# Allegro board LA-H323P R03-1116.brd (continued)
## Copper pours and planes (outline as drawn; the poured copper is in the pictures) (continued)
LX_1.8V on BOTTOM (solid shape): 180.19,85.17 180.19,84.05 180.44,83.81 180.44,81.38 180.25,81.19 178.32,81.19 178.18,81.32 178.18,82.26 178.42,82.5 179.17,82.5 179.32,82.64 179.32,85.15 179.49,85.32 180.04,85.32
LX_1V on TOP (solid shape): 185.2,96.91 185.2,95.59 185.03,95.42 182.26,95.42 182.17,95.51 182.17,96.84 182.39,97.06 185.05,97.06
LX_1V on BOTTOM (solid shape): 189.1,96.69 189.1,96.11 188.74,95.76 187.96,95.76 187.89,95.83 187.89,96 188.03,96.14 188.03,96.64 188.13,96.75 189.05,96.75
LX_1V on BOTTOM (solid shape): 183.97,98.33 183.97,96.86 184.27,96.56 185.12,96.56 185.71,95.97 185.71,95.38 185.65,95.32 184.76,95.32 184.73,95.35 183.99,95.35 183.78,95.14 183.78,95.14 183.71,95.07 183.71,92.99 183.51,92.79 180.83,92.79 180.7,92.92 180.7,98.17 180.99,98.46 183.84,98.46
LX_1V on IN2 (solid shape): 189.12,96.62 189.12,95.68 188.94,95.5 184.21,95.5 184.1,95.61 184.1,96.6 184.24,96.74 189,96.74
LX_2.5V on BOTTOM (solid shape): 4.43,44.38 4.43,43.04 4.52,42.95 5.99,42.95 6.08,42.86 6.08,41.89 5.99,41.8 2.61,41.8 2.52,41.89 2.52,42.6 2.61,42.69 3.45,42.69 3.54,42.78 3.54,44.38 3.63,44.47 4.34,44.47
LX_3V on BOTTOM (solid shape): 190.8,117.57 190.8,116.62 190.59,116.42 189.83,116.42 189.75,116.5 189.75,116.67 189.85,116.77 189.85,117.61 189.98,117.74 190.63,117.74
LX_3V on BOTTOM (solid shape): 186.26,120.39 186.26,119.09 186.45,118.9 187.02,118.9 187.1,118.82 187.1,117.09 187.56,116.63 187.56,116.04 187.49,115.97 185.63,115.97 185.57,115.91 185.57,114.19 185.39,114.02 183.33,114.02 183.21,114.14 183.21,117.24 183.98,118.02 183.98,120.29 184.23,120.54 186.11,120.54
LX_3V on IN2 (solid shape): 190.78,117.62 190.78,116.67 190.78,116.67 190.61,116.49 185.87,116.49 185.76,116.6 185.76,117.6 185.9,117.73 190.66,117.73
LX_5V on TOP (solid shape): 182.84,107.93 182.84,106.36 182.71,106.23 180.93,106.23 180.81,106.36 180.81,108.02 181.01,108.23 182.54,108.23
LX_5V on BOTTOM (solid shape): 182.16,109.33 182.16,105.08 182.64,104.59 182.88,104.59 182.88,104.6 186.61,104.6 186.61,104.07 182.45,104.07 182.28,103.89 179.2,103.89 179.11,103.98 179.11,108.89 179.61,109.38 182.1,109.38
LX_CHG on TOP (solid shape): 179.37,53.68 179.37,50.96 179.15,50.74 177.82,50.74 177.63,50.93 177.63,53.6 177.77,53.74 179.31,53.74
LX_CHG on BOTTOM (solid shape): 177.15,55.24 177.15,53.38 177.9,52.62 177.9,51.71 178.26,51.35 180.88,51.35 180.88,50.39 180.84,50.35 177.69,50.35 177.03,51.01 174.77,51.01 174.48,51.31 174.48,55.23 174.54,55.29 177.1,55.29
LX_CHG on BOTTOM (solid shape): 193.5,57.23 194.36,57.23 194.41,57.18 194.41,56.98 194.37,56.94 193.33,56.94 193.18,57.09 192.32,57.09 191.92,57.48 190.73,57.48 190.64,57.58 190.64,58.04 190.76,58.16 192.57,58.16
LX_CHG on IN2 (solid shape): 193.9,57.91 193.9,57.34 193.78,57.22 192.21,57.22 192.07,57.35 192.07,57.35 192.07,57.92 192.21,58.06 193.75,58.06
LX_CHG on IN2 (solid shape): 179.25,52.13 179.25,51.96 178.12,50.83 177.97,50.83 177.95,50.85 177.55,51.25 177.55,51.45 178.63,52.53 178.85,52.53
LX_DDR on TOP (solid shape): 8.04,68.41 8.04,66.38 7.64,65.98 6.36,65.98 6.1,66.24 6.1,68.39 6.2,68.49 7.96,68.49
LX_DDR on BOTTOM (solid shape): 12.3,69.04 12.3,65.3 12.17,65.17 3.61,65.17 3.61,66.19 6.08,66.19 8.35,68.46 8.35,69.34 8.5,69.49 11.85,69.49
LX_DDR on BOTTOM (solid shape): 10.17,73.74 10.17,73.6 11.34,72.43 11.34,71.66 11.29,71.61 10.22,71.61 9.89,71.93 9.89,72.99 9.67,73.21 9.67,74.03 9.7,74.05 9.86,74.05
LX_DDR on IN2 (solid shape): 7.73,67.29 7.73,66.17 7.6,66.04 6.49,66.04 6.33,66.2 6.33,67.28 6.46,67.41 7.6,67.41
LX_DDR on IN2 (solid shape): 10.83,73.08 10.83,71.19 10.76,71.11 10.23,71.11 9.9,71.45 9.9,73.3 10.03,73.43 10.48,73.43
LX_VRAM on TOP (solid shape): 185.31,140.82 185.31,139.89 184.97,139.55 182.76,139.55 182.65,139.66 182.65,140.95 182.75,141.05 185.07,141.05
LX_VRAM on BOTTOM (solid shape): 189.72,137.54 189.72,136.97 189.41,136.67 188.59,136.67 188.5,136.75 188.5,136.9 188.61,137.01 188.61,137.57 188.73,137.68 189.58,137.68
LX_VRAM on BOTTOM (solid shape): 185.4,140.94 185.4,140.36 185.21,140.36 184.99,140.15 184.99,139.37 185.18,139.18 185.78,139.18 185.87,139.09 185.87,137.35 186.34,136.88 186.34,136.3 186.28,136.23 185.66,136.23 185.58,136.24 185.5,136.23 185.15,136.23 185.07,136.24 184.99,136.23 184.82,136.23 184.82,136.23 184.42,136.23 184.23,136.04 180.46,136.04 180.35,136.14 180.35,141.07 180.51,141.23 185.11,141.23
LX_VRAM on IN2 (solid shape): 189.74,137.54 189.74,136.59 189.59,136.43 184.91,136.43 184.8,136.54 184.8,137.54 184.94,137.67 189.61,137.67
Net_7 on BOTTOM (solid shape): 207.37,123.86 196.37,123.86 196.37,134.86 207.37,134.86
P1 on TOP (solid shape): 187.06,55.47 188.6,55.47 188.73,55.34 188.73,54.48 189.01,54.2 189.01,52.6 188.88,52.47 185.99,52.47 185.86,52.6 185.86,53.66 185.15,54.38 185.15,56.15 185.28,56.28 186.25,56.28
P2 on TOP (solid shape): 189.72,58.44 189.72,56.03 189.59,55.9 187.18,55.9 186.67,56.41 184.83,56.41 184.7,56.54 184.7,57.06 185.61,57.06 185.61,57.83 184.7,57.83 184.7,58.44 184.83,58.57 189.59,58.57
PEX_PLLVDD_GPU on TOP (solid shape): 139.96,106.31 139.96,104.94 140.16,104.75 140.16,104.23 140.07,104.14 139.81,104.14 139.65,104.3 139.65,105.03 139.5,105.18 138.87,105.18 138.85,105.15 138.17,105.15 138.06,105.05 136.35,105.05 136.28,105.11 136.28,105.49 136.45,105.66 137.83,105.66 137.98,105.81 139.09,105.81 139.36,106.08 139.36,106.23 139.56,106.42 139.85,106.42
REGN_CHG on BOTTOM (solid shape): 194.39,55.66 194.39,55.14 193.77,54.52 193.77,53.25 193.69,53.17 192.01,53.17 191.91,53.27 191.91,54.28 192.01,54.38 192.63,54.38 193.49,55.25 193.49,55.64 193.57,55.72 194.34,55.72
RT3602_VIN on BOTTOM (solid shape): 194.74,69.48 195.1,69.48 195.19,69.39 196.47,69.39 196.52,69.34 196.52,68.57 196.44,68.49 196.34,68.49 196.27,68.56 196.27,68.96 196.22,69.01 194.75,69.01 194.65,69.1 193.06,69.1 192.73,68.77 192.73,68.24 192.68,68.19 191.93,68.19 191.86,68.26 191.86,69.68 191.89,69.7 194.51,69.7
SA_LG on BOTTOM (solid shape): 160.65,54.91 160.65,53.61 160.53,53.49 159.49,53.49 159.37,53.61 159.37,54.76 159.62,55.01 159.66,55.05 160.52,55.05
SA_LX on TOP (solid shape): 159.69,57.12 159.69,56.09 159.11,55.52 157.72,55.52 157.46,55.77 157.46,57.12 157.64,57.3 159.51,57.3
SA_LX on BOTTOM (solid shape): 159.75,57.3 159.75,56.52 159.98,56.28 162.54,56.28 162.59,56.28 162.62,56.26 162.62,55.31 162.57,55.27 159.62,55.27 158.73,54.38 156.95,54.38 156.78,54.55 156.78,55.87 157.69,55.87 157.69,56.69 156.78,56.69 156.78,57.76 157.08,58.06 158.99,58.06
SA_SNUB on TOP (solid shape): 162.67,57.17 162.67,55.32 162.49,55.14 160.26,55.14 160.13,55.27 160.13,57.17 160.26,57.3 162.54,57.3
SNB_1V on TOP (solid shape): 184.24,93.91 184.24,91.92 184,91.69 183.49,91.69 183.36,91.82 183.36,92.46 183.14,92.67 182.28,92.67 182.19,92.76 182.19,93.9 182.34,94.05 184.1,94.05
SNB_2.5V on BOTTOM (solid shape): 3.28,44.38 3.28,43.04 3.2,42.95 2.61,42.95 2.52,43.04 2.52,44.38 2.61,44.47 3.2,44.47
SNB_DDR on TOP (solid shape): 5.44,68.32 5.44,66 5.22,65.78 4.39,65.78 4.21,65.96 4.21,68.36 4.34,68.49 5.28,68.49
SNUB_1.8V on BOTTOM (solid shape): 179.18,84.31 179.18,82.76 179.14,82.72 178.19,82.72 178.1,82.81 178.1,84.37 178.17,84.44 179.05,84.44
SNUB_CHG on TOP (solid shape): 177.09,53.67 177.09,51.07 177.04,51.02 176.38,51.02 176.34,51.06 176.34,51.7 176.15,51.89 175.54,51.89 175.42,52.01 175.42,53.67 175.5,53.75 177.01,53.75
SNUB_NVVDD1 on TOP (solid shape): 115.43,125.75 115.43,125.12 115.55,124.99 115.81,124.99 115.93,124.86 115.93,123.21 115.87,123.15 114.85,123.15 114.79,123.21 114.79,125.75 114.85,125.81 115.36,125.81
SNUB_NVVDD2 on TOP (solid shape): 118.73,130.23 118.73,128.42 118.6,128.29 117.08,128.29 116.95,128.42 116.95,128.92 116.82,129.05 115.93,129.05 115.81,129.18 115.81,130.2 116.06,130.45 118.51,130.45
SNUB_VRAM on TOP (solid shape): 184.56,138.64 184.56,137.19 184.43,137.05 183.82,137.05 183.61,136.84 183.61,136.23 183.54,136.16 182.67,136.16 182.43,136.4 182.43,138.93 182.51,139.02 184.18,139.02
SPK_L+ on TOP (solid shape): 26.53,37.51 26.53,36.57 26.49,36.53 24.73,36.53 23.88,37.38 22.56,37.38 22.16,37.38 22.11,37.44 22.11,37.54 22.16,37.59 26.45,37.59
SPK_L+_CONN on TOP (solid shape): 29.28,37.42 29.28,36.66 29.16,36.53 27.26,36.53 27.2,36.59 27.2,37.5 27.25,37.55 29.16,37.55
SPK_L+_CONN on BOTTOM (solid shape): 30.17,37.36 30.17,36.69 30.08,36.59 28.11,36.59 28.01,36.69 28.01,37.36 28.14,37.49 30.05,37.49
SPK_L+_CONN on BOTTOM (solid shape): 100.08,98.36 100.08,97.78 100.72,97.15 100.72,95.1 100.47,94.85 100.47,93.55 100.47,93.54 100.47,93.24 100.2,92.97 99.67,92.97 99.6,93.03 99.6,93.94 99.68,94.01 99.68,95.4 99.87,95.59 99.87,96.43 98.93,97.37 98.93,98.55 99.08,98.7 99.74,98.7
SPK_L- on TOP (solid shape): 26.53,38.78 26.53,37.84 26.48,37.79 24.77,37.79 24.73,37.75 23.18,37.75 23.14,37.79 22.15,37.79 22.1,37.84 22.1,37.93 22.16,37.99 23.14,37.99 23.21,38.06 24.46,38.06 25.22,38.82 26.49,38.82
SPK_L-_CONN on TOP (solid shape): 29.28,38.69 29.28,37.93 29.16,37.8 27.25,37.8 27.19,37.87 27.19,38.77 27.23,38.82 29.16,38.82
SPK_L-_CONN on BOTTOM (solid shape): 30.17,38.66 30.17,37.93 30.08,37.84 28.11,37.84 28.01,37.93 28.01,38.63 28.15,38.77 30.07,38.77
SPK_L-_CONN on BOTTOM (solid shape): 98.08,98.37 98.08,97.48 97.74,97.14 97.74,93.72 97.76,93.7 97.76,93.26 97.56,93.06 96.99,93.06 96.66,93.39 96.66,94.55 96.86,94.76 96.86,98.54 97.06,98.74 97.71,98.74
SPK_R+ on TOP (solid shape): 26.54,41.29 26.54,40.4 26.48,40.34 25.35,40.34 23.59,38.59 22.15,38.59 22.1,38.63 22.1,38.74 22.16,38.79 23.29,38.79 23.62,39.12 23.62,39.37 25.6,41.36 26.48,41.36
SPK_R+_CONN on TOP (solid shape): 29.25,41.26 29.25,40.44 29.16,40.34 27.25,40.34 27.19,40.41 27.19,41.29 27.25,41.36 29.16,41.36
SPK_R+_CONN on BOTTOM (solid shape): 30.17,41.23 30.17,40.47 30.05,40.34 28.14,40.34 28.01,40.47 28.01,41.23 28.14,41.36 30.05,41.36
SPK_R+_CONN on BOTTOM (solid shape): 95.55,98.29 95.55,94.32 95.18,93.96 94.75,93.96 94.62,94.08 94.62,97.02 94.32,97.31 94.32,98.49 94.45,98.62 94.47,98.62 94.58,98.74 95.1,98.74
SPK_R- on TOP (solid shape): 26.54,40.03 26.54,39.12 26.49,39.07 25.22,39.07 24.34,38.19 23.15,38.19 23.15,38.18 22.17,38.18 22.11,38.24 22.11,38.34 22.16,38.39 23.67,38.39 25.36,40.09 26.49,40.09
SPK_R-_CONN on TOP (solid shape): 29.26,39.98 29.26,39.17 29.16,39.07 27.27,39.07 27.19,39.15 27.19,40.04 27.23,40.09 29.16,40.09
SPK_R-_CONN on BOTTOM (solid shape): 30.17,39.96 30.17,39.2 30.05,39.07 26.78,39.07 26.65,39.2 26.65,39.96 26.78,40.09 30.05,40.09
SPK_R-_CONN on BOTTOM (solid shape): 93.44,98.5 93.44,97.04 92.9,96.49 92.9,96.35 92.54,96 92.54,95.64 92.79,95.38 92.79,94.23 92.63,94.06 92.15,94.06 91.96,94.25 91.96,95.23 91.75,95.44 91.75,96.37 92.36,96.98 92.36,98.41 92.68,98.72 93.21,98.72
UG_CHG on BOTTOM (solid shape): 178.57,54.88 178.57,53.55 178.9,53.22 178.9,52.57 178.79,52.46 178.32,52.46 177.68,53.1 177.68,54.9 177.8,55.01 178.44,55.01
UG_CHG on BOTTOM (solid shape): 193.33,56.72 194.34,56.72 194.41,56.64 194.41,56.53 194.32,56.44 191.82,56.44 191.72,56.54 191.72,56.91 191.77,56.96
UG_CHG on IN2 (solid shape): 192.76,56.89 192.76,56.52 192.38,56.14 190.62,56.14 190.48,56.28 190.48,56.78 190.75,57.05 192.61,57.05
UG_CHG on IN2 (solid shape): 179.41,55.74 179.41,55.41 178.57,54.57 178.57,53.96 178.48,53.87 177.86,53.87 177.74,53.98 177.74,54.9 177.81,54.96 177.81,54.98 178.85,56.03 179.12,56.03
UG_DDR on BOTTOM (solid shape): 4.13,68.47 4.13,67.4 4,67.27 3.93,67.27 3.92,67.27 3.41,67.27 3.03,67.65 3.03,68.42 3.16,68.55 4.04,68.55
UG_DDR on BOTTOM (solid shape): 9.51,74 9.51,73.19 9.72,72.97 9.72,71.97 9.72,71.95 9.65,71.87 9.35,71.87 9.23,71.99 9.23,73.05 9.27,73.09 9.27,74 9.32,74.05 9.46,74.05
UG_DDR on IN2 (solid shape): 4.47,69.19 4.47,68.99 4.05,68.57 4.05,67.76 3.81,67.52 3.14,67.52 3.02,67.64 3.02,68.71 3.93,69.62 4.05,69.62
UG_DDR on IN2 (solid shape): 9.75,72.98 9.75,71.46 9.45,71.16 8.82,71.16 8.61,71.37 8.61,71.7 9.04,72.12 9.04,72.89 9.25,73.1 9.62,73.1
VID_PLLVDD on TOP (solid shape): 146,99.57 146.64,99.57 146.82,99.57 146.82,99.57 146.85,99.54 146.85,97.91 146.59,97.65 146.15,97.65 146.03,97.77 146.03,98.08 146.02,98.09 146.02,98.14 145.81,98.34 145.81,99.51 145.88,99.57
VID_PLLVDD on BOTTOM (solid shape): 130.54,94.49 130.54,93.11 130.41,92.98 125.84,92.98 125.71,93.11 125.71,94.36 125.97,94.61 130.41,94.61
VID_PLLVDD on BOTTOM (solid shape): 147.03,98.49 147.03,98.22 146.53,97.73 146.32,97.73 145.83,98.21 145.83,98.48 146.33,98.97 146.54,98.97
VID_PLLVDD on BOTTOM (solid shape): 140.61,93.26 140.91,93.26 140.92,93.25 141.37,93.25 141.59,93.03 141.59,92.41 141.5,92.41 141.5,92.32 141.13,91.95 140.2,91.95 139.68,92.46 139.43,92.46 138.98,92.9 138.98,93.3 139.24,93.56 140.31,93.56
VID_PLLVDD on IN1 (solid shape): 146.86,98.81 146.86,93.73 145.53,92.4 141.38,92.4 140.73,93.05 140.73,93.57 141.66,94.5 144.35,94.5 144.59,94.73 145.24,94.73 145.24,94.68 145.24,94.63 145.26,94.58 145.28,94.53 145.31,94.49 145.35,94.45 145.39,94.41 145.44,94.39 145.49,94.37 145.54,94.36 145.59,94.35 145.65,94.36 145.7,94.37 145.75,94.39 145.79,94.41 145.83,94.45 145.87,94.49 145.9,94.53 145.92,94.58 145.94,94.63 145.95,94.68 145.95,94.73 145.94,94.79 145.92,94.84 145.9,94.89 145.87,94.93 145.83,94.97 145.79,95 145.75,95.03 145.7,95.05 145.65,95.06 145.59,95.06 145.54,95.06 145.49,95.05 145.44,95.03 145.39,95 145.35,94.97 145.31,94.93 145.28,94.89 145.26,94.84 145.24,94.79 145.24,94.73 144.59,94.73 145.9,96.05 145.9,97.71 145.91,97.73 145.94,97.79 145.95,97.84 145.95,97.9 145.95,97.95 145.94,98.01 145.91,98.06 145.9,98.09 145.9,98.75 146.16,99.01 146.67,99.01
VTTREF_DDR on BOTTOM (solid shape): 7.01,75.66 7.85,75.66 7.88,75.63 7.88,75.5 7.83,75.44 6.93,75.44 6.69,75.21 5.92,75.21 5.87,75.25 5.87,75.85 5.89,75.87 6.8,75.87
N19936727 on BOTTOM (solid shape): 180.59,72.84 180.59,71.34 179.91,70.67 179.91,70.51 179.83,70.42 179.53,70.42 179.42,70.53 179.42,71.67 179.67,71.92 179.67,72.84 179.74,72.9 180.52,72.9
N19936733 on BOTTOM (solid shape): 179.24,68.95 179.24,68.24 179.24,68.23 179.24,67.63 179.14,67.52 177.93,67.52 177.86,67.58 177.86,68.97 178,69.11 179.07,69.11
N44699188 on TOP (solid shape): 228.33,19.71 228.33,18.94 227.95,18.56 227.95,17.8 227.69,17.55 226.88,17.55 226.44,17.99 226.44,19.58 226.42,19.6 226.42,19.9 226.49,19.96 228.07,19.96
N91785360 on TOP (solid shape): 22.46,123.34 22.46,110.64 22.33,110.51 20.96,110.51 20.92,110.55 20.92,111.17 20.96,111.26 21.06,111.27 21.47,111.4 21.46,111.83 21.43,111.89 21.54,112.19 21.43,112.48 21.54,112.77 21.43,113.06 21.46,113.13 21.47,113.56 21.06,113.69 20.96,113.7 20.92,113.78 20.92,114.22 20.96,114.31 21.06,114.32 21.47,114.44 21.46,114.88 21.43,114.94 21.54,115.23 21.43,115.53 21.54,115.82 21.44,116.11 21.46,116.17 21.48,116.61 21.06,116.73 20.96,116.74 20.92,116.83 20.92,117.27 20.96,117.35 21.06,117.37 21.47,117.49 21.46,117.93 21.43,117.99 21.54,118.28 21.43,118.57 21.54,118.87 21.43,119.16 21.46,119.22 21.47,119.66 21.06,119.78 20.96,119.8 20.92,119.88 20.92,120.32 20.96,120.4 21.06,120.41 21.47,120.54 21.46,120.97 21.43,121.04 21.54,121.33 21.43,121.62 21.46,121.69 21.54,121.93 21.44,122.16 21.41,122.22 21.43,122.29 21.38,122.77 20.9,122.75 20.83,122.73 20.76,122.76 20.56,122.96 20.56,123.34 20.68,123.46 22.33,123.46

Small or netless copper shapes (teardrops, artwork), in the pictures only: 110 on TOP, 48 on BOTTOM, 3 on IN1, 1 on IN2

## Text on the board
Ref Des/Silkscreen Bottom: H4 | H5 | 1 | FPR | 2
User.Comments: CR_PUZ1_1 | LA-H323P | 2019-11-16 | 2018-11-16 | Voilin | FPW50
XSECTION_CHART: * | L1: TOP | L2: VCC | L3: IN1 | L4: IN2 | L5: GND | L6: BOTTOM | DESIGN CROSS SECTION CHART | ___________________________ | TOTAL THICKNESS 46.32 MIL | 1-6
User.39: HR_1_2mm-6L and 8L and 10L(4mil & 5mil 50ohm)_180828.pdf | L2-VCC | L3-IN1 | L4-IN2 | L1-TOP | L5-GND | L6-BOT | LAYER | NAME | STACKUP: 6 LAYER | trace wide | 45 ohm | 6.2 | 5 | 50 ohm | 4 | THICKNESS=1.2mm | 5.5/4.5 | 80ohm | 4.3/4 | wide/space | 85 ohm | 4/4.5 | 5/5 | 90 ohm | 4/6.5 | 100 ohm | 3.5/10 | 4/8 | L2/L5 | Ref | L2 | L5
User.40: FIGURE | SIZE | 8.0 | 16.0 | 22.0 | 35.0 | 43.0 | 91.0 | 98.0 | 126.0 | 197.0 | 26.0 | 63.0 | 35.0x16.0 | 43.0x20.0 | 55.0x39.0 | 59.0x20.0 | 63.0x35.0 | 79.0x24.0 | 114.0x35.0 | 33.0x26.0 | 110.0x98.0 | DRILL CHART: TOP to BOTTOM | ALL UNITS ARE IN MILS | TOLERANCE | +3.0/-3.0 | +2.0/-2.0 | PLATED | NON-PLATED | QTY | 5804 | 10 | 19 | 8 | 3 | 1 | 2 | 6 | 4
User.42: STACK-UP SETTING OK
